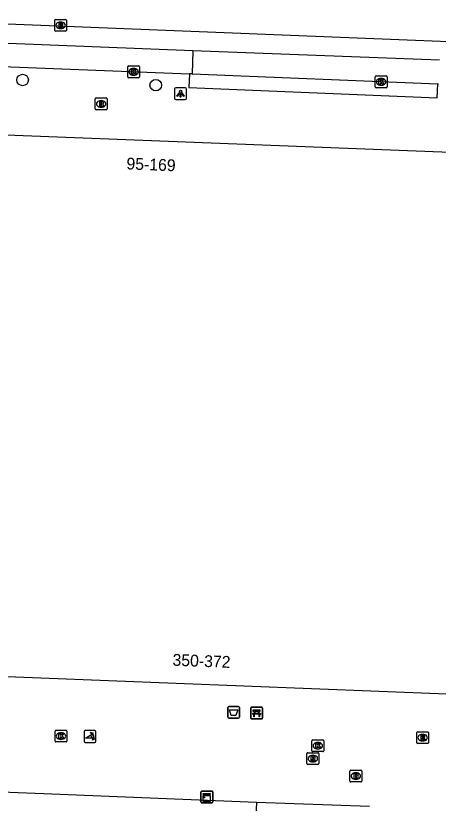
# Model space of a CAD drawing. Extents: x 160891 to 161384, y 386490 to 386907.
# Drawn here: x 161140.9 to 161176.7, y 386833.9 to 386900.6 of the extents above; entities that cross this region are included whole.
import ezdxf

# ---------------------------------------------------------------- set-up
doc = ezdxf.new("R2010")
doc.units = 0
for name, color, linetype in [('IMGEO_Afvalbak', 7, 'Continuous'), ('IMGEO_Bank', 7, 'Continuous'), ('IMGEO_Boom', 7, 'Continuous'), ('IMGEO_Brandkraan', 7, 'Continuous'), ('IMGEO_Kast', 7, 'Continuous'), ('IMGEO_Kolk', 7, 'Continuous'), ('IMGEO_Lichtpunt', 7, 'Continuous'), ('IMGEO_Pand', 7, 'Continuous'), ('IMGEO_Pand_nummerreeks', 7, 'Continuous'), ('IMGEO_Poller', 7, 'Continuous'), ('IMGEO_Rijbaan_lokaal_gesloten', 7, 'Continuous'), ('IMGEO_Rioolput', 7, 'Continuous'), ('IMGEO_Voetpad_open', 7, 'Continuous')]:
    doc.layers.add(name, color=color, linetype=linetype)

msp = doc.modelspace()

# ---------------------------------------------------------------- linework, layer by layer
at = {"layer": 'IMGEO_Afvalbak'}
for p, q in [((161158.851, 386841.169), (161158.851, 386841.969)), ((161158.851, 386841.969), (161158.851, 386841.169)), ((161158.951, 386842.069), (161159.741, 386842.069)), ((161159.741, 386842.069), (161158.951, 386842.069)), ((161159.841, 386841.969), (161159.841, 386841.169)), ((161159.841, 386841.169), (161159.841, 386841.969)), ((161159.741, 386841.069), (161158.951, 386841.069)), ((161158.951, 386841.069), (161159.741, 386841.069))]:
    msp.add_line(p, q, dxfattribs=at)
msp.add_lwpolyline([(161158.994, 386841.783), (161159.698, 386841.783), (161159.549, 386841.313), (161159.143, 386841.313), (161158.994, 386841.783)], dxfattribs=at)
for centre, start, end in [((161158.951, 386841.969), 90, 180), ((161158.951, 386841.969), 90, 180), ((161159.741, 386841.969), 0, 90), ((161159.741, 386841.969), 360, 90), ((161158.951, 386841.169), 180, 270), ((161158.951, 386841.169), 180, 270), ((161159.741, 386841.169), 270, 0), ((161159.741, 386841.169), 270, 0)]:
    msp.add_arc(centre, 0.1, start, end, dxfattribs=at)
at = {"layer": 'IMGEO_Bank'}
for p, q in [((161160.805, 386841.088), (161160.805, 386841.929)), ((161160.805, 386841.929), (161160.805, 386841.088)), ((161160.88, 386842.013), (161161.721, 386842.013)), ((161161.721, 386842.013), (161160.88, 386842.013)), ((161161.114, 386841.519), (161161.114, 386841.625)), ((161161.158, 386841.625), (161161.158, 386841.519)), ((161161.446, 386841.631), (161161.164, 386841.631)), ((161161.164, 386841.513), (161161.446, 386841.513)), ((161161.452, 386841.519), (161161.452, 386841.625)), ((161161.496, 386841.625), (161161.496, 386841.519)), ((161161.805, 386841.938), (161161.805, 386841.097)), ((161161.805, 386841.097), (161161.805, 386841.938)), ((161161.73, 386841.013), (161160.889, 386841.013)), ((161160.889, 386841.013), (161161.73, 386841.013)), ((161161.502, 386841.411), (161161.109, 386841.411))]:
    msp.add_line(p, q, dxfattribs=at)
for points in [[(161161.052, 386841.411), (161160.91, 386841.411), (161161.022, 386841.513), (161161.108, 386841.513)], [(161161.108, 386841.631), (161161.022, 386841.631), (161161.022, 386841.792), (161161.585, 386841.792), (161161.585, 386841.631), (161161.502, 386841.631)], [(161161.502, 386841.513), (161161.585, 386841.513), (161161.697, 386841.411), (161161.558, 386841.411)], [(161161.102, 386841.404), (161161.102, 386841.197), (161161.059, 386841.197), (161161.059, 386841.404)], [(161161.552, 386841.404), (161161.552, 386841.197), (161161.508, 386841.197), (161161.508, 386841.404)]]:
    msp.add_lwpolyline(points, dxfattribs=at)
for centre, radius, start, end in [((161160.883, 386841.935), 0.0779, 92.4484, 184.28452), ((161160.883, 386841.935), 0.0779, 92.4484, 184.28452), ((161161.107, 386841.624), 0.00671, 2.89567, 87.10433), ((161161.107, 386841.52), 0.00671, 272.89567, 357.10433), ((161161.164, 386841.624), 0.00671, 92.89567, 177.10433), ((161161.164, 386841.52), 0.00671, 182.89567, 267.10433), ((161161.446, 386841.624), 0.00671, 2.89567, 87.10433), ((161161.446, 386841.52), 0.00671, 272.89567, 357.10433), ((161161.503, 386841.624), 0.00671, 92.89567, 177.10433), ((161161.503, 386841.52), 0.00671, 182.89567, 267.10433), ((161161.727, 386841.935), 0.0779, 2.4484, 94.28452), ((161161.727, 386841.935), 0.0779, 2.4484, 94.28452), ((161160.883, 386841.091), 0.0779, 182.4484, 274.28452), ((161160.883, 386841.091), 0.0779, 182.4484, 274.28452), ((161161.052, 386841.404), 0.00671, 2.89567, 87.10433), ((161161.109, 386841.404), 0.00671, 92.89567, 177.10433), ((161161.501, 386841.404), 0.00671, 2.89567, 87.10433), ((161161.558, 386841.404), 0.00671, 92.89567, 177.10433), ((161161.727, 386841.091), 0.0779, 272.4484, 4.28452), ((161161.727, 386841.091), 0.0779, 272.4484, 4.28452)]:
    msp.add_arc(centre, radius, start, end, dxfattribs=at)
at = {"layer": 'IMGEO_Boom'}
for centre in [(161141.488, 386895.12), (161152.761, 386894.677)]:
    msp.add_circle(centre, 0.489, dxfattribs=at)
at = {"layer": 'IMGEO_Brandkraan'}
for p, q in [((161147.635, 386892.671), (161147.635, 386893.523)), ((161147.71, 386893.597), (161148.562, 386893.597)), ((161148.636, 386893.523), (161148.636, 386892.671)), ((161148.146, 386892.817), (161148.121, 386892.817)), ((161148.123, 386893.377), (161148.148, 386893.377)), ((161148.562, 386892.597), (161147.71, 386892.597)), ((161169.199, 386835.749), (161169.199, 386836.601)), ((161169.274, 386836.675), (161170.126, 386836.675)), ((161169.687, 386836.455), (161169.712, 386836.455)), ((161170.2, 386836.601), (161170.2, 386835.749)), ((161170.126, 386835.675), (161169.274, 386835.675)), ((161169.71, 386835.895), (161169.685, 386835.895))]:
    msp.add_line(p, q, dxfattribs=at)
for points in [[(161147.635, 386892.671), (161147.635, 386893.523)], [(161147.71, 386893.597), (161148.562, 386893.597)], [(161148.636, 386893.523), (161148.636, 386892.671)], [(161147.983, 386893.297), (161147.983, 386892.897), (161148.196, 386892.897)], [(161148.214, 386893.297), (161147.983, 386893.297)], [(161148.162, 386893.216), (161148.108, 386893.216), (161148.108, 386893.14)], [(161148.108, 386893.14), (161148.161, 386893.14)], [(161148.17, 386893.064), (161148.108, 386893.064), (161148.108, 386892.983)], [(161148.108, 386892.983), (161148.17, 386892.983)], [(161148.562, 386892.597), (161147.71, 386892.597)], [(161169.199, 386835.749), (161169.199, 386836.601)], [(161169.274, 386836.675), (161170.126, 386836.675)], [(161169.547, 386836.375), (161169.547, 386835.975), (161169.76, 386835.975)], [(161169.778, 386836.375), (161169.547, 386836.375)], [(161169.726, 386836.294), (161169.672, 386836.294), (161169.672, 386836.218)], [(161169.672, 386836.218), (161169.725, 386836.218)], [(161169.734, 386836.142), (161169.672, 386836.142), (161169.672, 386836.061)], [(161170.2, 386836.601), (161170.2, 386835.749)], [(161170.126, 386835.675), (161169.274, 386835.675)], [(161169.672, 386836.061), (161169.734, 386836.061)]]:
    msp.add_lwpolyline(points, dxfattribs=at)
for centre, radius, start, end in [((161147.712, 386893.521), 0.0765, 91.55205, 178.44795), ((161147.712, 386893.521), 0.0765, 91.55205, 178.44795), ((161148.56, 386893.521), 0.0765, 1.55205, 88.44795), ((161148.56, 386893.521), 0.0765, 1.55205, 88.44795), ((161148.163, 386893.178), 0.0379, 267.82845, 90.93552), ((161148.171, 386893.023), 0.0404, 269.87594, 90.50774), ((161148.202, 386893.148), 0.251, 268.66757, 293.53466), ((161148.218, 386893.152), 0.145, 59.4692, 91.53667), ((161148.243, 386893.199), 0.0922, 285.51372, 58.15012), ((161148.248, 386893.007), 0.105, 301.31148, 78.98903), ((161147.712, 386892.673), 0.0765, 181.55205, 268.44795), ((161147.712, 386892.673), 0.0765, 181.55205, 268.44795), ((161148.56, 386892.673), 0.0765, 271.55205, 358.44795), ((161148.56, 386892.673), 0.0765, 271.55205, 358.44795), ((161169.276, 386836.599), 0.0765, 91.55205, 178.44795), ((161169.276, 386836.599), 0.0765, 91.55205, 178.44795), ((161169.727, 386836.256), 0.0379, 267.82845, 90.93552), ((161169.735, 386836.101), 0.0404, 269.87594, 90.50774), ((161169.782, 386836.23), 0.145, 59.4692, 91.53667), ((161169.807, 386836.277), 0.0922, 285.51372, 58.15012), ((161169.812, 386836.085), 0.105, 301.31148, 78.98903), ((161170.124, 386836.599), 0.0765, 1.55205, 88.44795), ((161170.124, 386836.599), 0.0765, 1.55205, 88.44795), ((161169.276, 386835.751), 0.0765, 181.55205, 268.44795), ((161169.276, 386835.751), 0.0765, 181.55205, 268.44795), ((161169.766, 386836.226), 0.251, 268.66757, 293.53466), ((161170.124, 386835.751), 0.0765, 271.55205, 358.44795), ((161170.124, 386835.751), 0.0765, 271.55205, 358.44795)]:
    msp.add_arc(centre, radius, start, end, dxfattribs=at)
for centre, major_axis, ratio, start_param, end_param in [((161148.122, 386893.097), (-0.387, 0.002), 0.722429, 4.712389, 7.853982), ((161148.147, 386893.097), (-0.39, 0.002), 0.717154, 1.570796, 4.712389), ((161169.686, 386836.175), (-0.387, 0.002), 0.722429, 4.712389, 7.853982), ((161169.711, 386836.175), (-0.39, 0.002), 0.717154, 1.570796, 4.712389)]:
    msp.add_ellipse(centre, major_axis=major_axis, ratio=ratio, start_param=start_param, end_param=end_param, dxfattribs=at)
at = {"layer": 'IMGEO_Kast'}
for p, q in [((161156.584, 386833.979), (161156.584, 386834.82)), ((161156.584, 386834.82), (161156.584, 386833.979)), ((161156.659, 386834.904), (161157.5, 386834.904)), ((161157.5, 386834.904), (161156.659, 386834.904)), ((161157.584, 386834.829), (161157.584, 386833.988)), ((161157.584, 386833.988), (161157.584, 386834.829)), ((161157.509, 386833.904), (161156.668, 386833.904)), ((161156.668, 386833.904), (161157.509, 386833.904))]:
    msp.add_line(p, q, dxfattribs=at)
for points in [[(161156.779, 386834.694), (161157.379, 386834.694), (161157.379, 386834.609), (161156.779, 386834.609), (161156.779, 386834.694)], [(161156.779, 386834.519), (161157.379, 386834.519), (161157.379, 386834.03), (161156.779, 386834.03), (161156.779, 386834.519)]]:
    msp.add_lwpolyline(points, dxfattribs=at)
msp.add_circle((161156.863, 386834.368), 0.0377, dxfattribs=at)
for centre, start, end in [((161156.662, 386834.826), 92.4484, 184.28452), ((161156.662, 386834.826), 92.4484, 184.28452), ((161157.506, 386834.826), 2.4484, 94.28452), ((161157.506, 386834.826), 2.4484, 94.28452), ((161156.662, 386833.982), 182.4484, 274.28452), ((161156.662, 386833.982), 182.4484, 274.28452), ((161157.506, 386833.982), 272.4484, 4.28452), ((161157.506, 386833.982), 272.4484, 4.28452)]:
    msp.add_arc(centre, 0.0779, start, end, dxfattribs=at)
at = {"layer": 'IMGEO_Kolk'}
for p, q in [((161150.383, 386895.385), (161150.383, 386896.237)), ((161150.458, 386896.311), (161151.31, 386896.311)), ((161151.384, 386896.237), (161151.384, 386895.385)), ((161150.894, 386895.531), (161150.869, 386895.531)), ((161150.871, 386896.091), (161150.896, 386896.091)), ((161151.31, 386895.311), (161150.458, 386895.311)), ((161171.341, 386894.538), (161171.341, 386895.39)), ((161171.416, 386895.464), (161172.268, 386895.464)), ((161171.829, 386895.244), (161171.854, 386895.244)), ((161172.342, 386895.39), (161172.342, 386894.538)), ((161172.268, 386894.464), (161171.416, 386894.464)), ((161171.852, 386894.684), (161171.827, 386894.684)), ((161144.236, 386839.134), (161144.236, 386839.986)), ((161144.311, 386840.06), (161145.163, 386840.06)), ((161144.724, 386839.84), (161144.749, 386839.84)), ((161145.237, 386839.986), (161145.237, 386839.134)), ((161145.163, 386839.06), (161144.311, 386839.06)), ((161144.747, 386839.28), (161144.722, 386839.28)), ((161165.987, 386838.316), (161165.987, 386839.168)), ((161166.062, 386839.242), (161166.914, 386839.242)), ((161166.475, 386839.022), (161166.5, 386839.022)), ((161166.988, 386839.168), (161166.988, 386838.316)), ((161166.914, 386838.242), (161166.062, 386838.242)), ((161166.498, 386838.462), (161166.473, 386838.462))]:
    msp.add_line(p, q, dxfattribs=at)
for points in [[(161150.383, 386895.385), (161150.383, 386896.237)], [(161150.458, 386896.311), (161151.31, 386896.311)], [(161151.384, 386896.237), (161151.384, 386895.385)], [(161150.704, 386896.011), (161150.827, 386896.011), (161150.827, 386895.86), (161150.957, 386896.011), (161151.121, 386896.011), (161150.975, 386895.86), (161151.128, 386895.611), (161150.976, 386895.611), (161150.891, 386895.775), (161150.827, 386895.708), (161150.827, 386895.611), (161150.704, 386895.611), (161150.704, 386896.011)], [(161151.31, 386895.311), (161150.458, 386895.311)], [(161171.341, 386894.538), (161171.341, 386895.39)], [(161171.416, 386895.464), (161172.268, 386895.464)], [(161171.662, 386895.164), (161171.785, 386895.164), (161171.785, 386895.013), (161171.915, 386895.164), (161172.079, 386895.164), (161171.933, 386895.013), (161172.086, 386894.764), (161171.934, 386894.764), (161171.849, 386894.928), (161171.785, 386894.861), (161171.785, 386894.764), (161171.662, 386894.764), (161171.662, 386895.164)], [(161172.342, 386895.39), (161172.342, 386894.538)], [(161172.268, 386894.464), (161171.416, 386894.464)], [(161144.236, 386839.134), (161144.236, 386839.986)], [(161144.311, 386840.06), (161145.163, 386840.06)], [(161144.557, 386839.76), (161144.68, 386839.76), (161144.68, 386839.609), (161144.81, 386839.76), (161144.974, 386839.76), (161144.828, 386839.609), (161144.981, 386839.36), (161144.829, 386839.36), (161144.744, 386839.524), (161144.68, 386839.457), (161144.68, 386839.36), (161144.557, 386839.36), (161144.557, 386839.76)], [(161145.237, 386839.986), (161145.237, 386839.134)], [(161145.163, 386839.06), (161144.311, 386839.06)], [(161165.987, 386838.316), (161165.987, 386839.168)], [(161166.062, 386839.242), (161166.914, 386839.242)], [(161166.308, 386838.942), (161166.431, 386838.942), (161166.431, 386838.791), (161166.561, 386838.942), (161166.725, 386838.942), (161166.579, 386838.791), (161166.732, 386838.542), (161166.58, 386838.542), (161166.495, 386838.706), (161166.431, 386838.639), (161166.431, 386838.542), (161166.308, 386838.542), (161166.308, 386838.942)], [(161166.988, 386839.168), (161166.988, 386838.316)], [(161166.914, 386838.242), (161166.062, 386838.242)]]:
    msp.add_lwpolyline(points, dxfattribs=at)
for centre, start, end in [((161150.46, 386896.235), 91.55205, 178.44795), ((161150.46, 386896.235), 91.55205, 178.44795), ((161151.308, 386896.235), 1.55205, 88.44795), ((161151.308, 386896.235), 1.55205, 88.44795), ((161150.46, 386895.387), 181.55205, 268.44795), ((161150.46, 386895.387), 181.55205, 268.44795), ((161151.308, 386895.387), 271.55205, 358.44795), ((161151.308, 386895.387), 271.55205, 358.44795), ((161171.418, 386895.388), 91.55205, 178.44795), ((161171.418, 386895.388), 91.55205, 178.44795), ((161172.266, 386895.388), 1.55205, 88.44795), ((161172.266, 386895.388), 1.55205, 88.44795), ((161171.418, 386894.54), 181.55205, 268.44795), ((161171.418, 386894.54), 181.55205, 268.44795), ((161172.266, 386894.54), 271.55205, 358.44795), ((161172.266, 386894.54), 271.55205, 358.44795), ((161144.313, 386839.984), 91.55205, 178.44795), ((161144.313, 386839.984), 91.55205, 178.44795), ((161145.161, 386839.984), 1.55205, 88.44795), ((161145.161, 386839.984), 1.55205, 88.44795), ((161144.313, 386839.136), 181.55205, 268.44795), ((161144.313, 386839.136), 181.55205, 268.44795), ((161145.161, 386839.136), 271.55205, 358.44795), ((161145.161, 386839.136), 271.55205, 358.44795), ((161166.064, 386839.166), 91.55205, 178.44795), ((161166.064, 386839.166), 91.55205, 178.44795), ((161166.912, 386839.166), 1.55205, 88.44795), ((161166.912, 386839.166), 1.55205, 88.44795), ((161166.064, 386838.318), 181.55205, 268.44795), ((161166.064, 386838.318), 181.55205, 268.44795), ((161166.912, 386838.318), 271.55205, 358.44795), ((161166.912, 386838.318), 271.55205, 358.44795)]:
    msp.add_arc(centre, 0.0765, start, end, dxfattribs=at)
for centre, major_axis, ratio, start_param, end_param in [((161150.87, 386895.811), (-0.387, 0.002), 0.722429, 4.712389, 7.853982), ((161150.895, 386895.811), (-0.39, 0.002), 0.717154, 1.570796, 4.712389), ((161171.828, 386894.964), (-0.387, 0.002), 0.722429, 4.712389, 7.853982), ((161171.853, 386894.964), (-0.39, 0.002), 0.717154, 1.570796, 4.712389), ((161144.723, 386839.56), (-0.387, 0.002), 0.722429, 4.712389, 7.853982), ((161144.748, 386839.56), (-0.39, 0.002), 0.717154, 1.570796, 4.712389), ((161166.474, 386838.742), (-0.387, 0.002), 0.722429, 4.712389, 7.853982), ((161166.499, 386838.742), (-0.39, 0.002), 0.717154, 1.570796, 4.712389)]:
    msp.add_ellipse(centre, major_axis=major_axis, ratio=ratio, start_param=start_param, end_param=end_param, dxfattribs=at)
at = {"layer": 'IMGEO_Lichtpunt'}
for p, q in [((161154.357, 386894.358), (161154.357, 386893.551)), ((161154.357, 386894.358), (161154.357, 386893.551)), ((161155.259, 386894.453), (161154.451, 386894.453)), ((161155.259, 386894.453), (161154.451, 386894.453)), ((161155.353, 386893.551), (161155.353, 386894.358)), ((161155.353, 386893.551), (161155.353, 386894.358)), ((161154.451, 386893.457), (161155.259, 386893.457)), ((161154.451, 386893.457), (161155.259, 386893.457))]:
    msp.add_line(p, q, dxfattribs=at)
for points in [[(161154.731, 386894.022), (161154.77, 386893.994), (161154.582, 386893.732), (161154.544, 386893.759), (161154.731, 386894.022)], [(161154.833, 386893.974), (161154.88, 386893.974), (161154.88, 386893.652), (161154.833, 386893.652), (161154.833, 386893.974)], [(161154.943, 386893.994), (161154.981, 386894.021), (161155.168, 386893.759), (161155.129, 386893.731), (161154.943, 386893.994)]]:
    msp.add_lwpolyline(points, dxfattribs=at)
msp.add_circle((161154.856, 386894.156), 0.0994, dxfattribs=at)
for centre, start, end in [((161154.451, 386894.358), 90, 180), ((161154.451, 386894.358), 90, 180), ((161155.259, 386894.358), 0, 90), ((161155.259, 386894.358), 0, 90), ((161154.451, 386893.551), 180, 270), ((161154.451, 386893.551), 180, 270), ((161155.259, 386893.551), 270, 0), ((161155.259, 386893.551), 270, 360)]:
    msp.add_arc(centre, 0.0946, start, end, dxfattribs=at)
at = {"layer": 'IMGEO_Pand'}
for points in [[(161196.381, 386887.886), (161196.395, 386888.23), (161188.186, 386888.554), (161178.427, 386888.94), (161127.058, 386890.969)], [(161194.586, 386842.427), (161120.067, 386845.369), (161120.551, 386857.609)], [(161139.684, 386834.849), (161143.958, 386834.674), (161161.282, 386833.963)], [(161161.282, 386833.963), (161160.709, 386819.875), (161160.411, 386812.554), (161160.119, 386805.384), (161159.627, 386793.285), (161159.236, 386783.673), (161158.95, 386776.656), (161158.648, 386769.233), (161158.228, 386758.915)]]:
    msp.add_lwpolyline(points, dxfattribs=at)
at = {"layer": 'IMGEO_Poller'}
for p, q in [((161146.698, 386839.927), (161146.698, 386839.12)), ((161146.698, 386839.927), (161146.698, 386839.12)), ((161147.6, 386840.022), (161146.792, 386840.022)), ((161147.6, 386840.022), (161146.792, 386840.022)), ((161147.694, 386839.12), (161147.694, 386839.927)), ((161147.694, 386839.12), (161147.694, 386839.927)), ((161146.792, 386839.025), (161147.6, 386839.025)), ((161146.792, 386839.025), (161147.6, 386839.025))]:
    msp.add_line(p, q, dxfattribs=at)
for points in [[(161147.333, 386839.378), (161146.82, 386839.378), (161147.25, 386839.653)], [(161147.377, 386839.751), (161147.365, 386839.678), (161147.24, 386839.883)], [(161147.24, 386839.883), (161147.471, 386839.817), (161147.4, 386839.785)], [(161147.393, 386839.206), (161147.459, 386839.437), (161147.489, 386839.369)], [(161147.525, 386839.342), (161147.597, 386839.331), (161147.393, 386839.206)]]:
    msp.add_lwpolyline(points, dxfattribs=at)
for centre, radius, start, end in [((161146.792, 386839.927), 0.0946, 90, 180), ((161146.792, 386839.927), 0.0946, 90, 180), ((161147.005, 386839.428), 0.332, 351.32473, 42.4854), ((161147.019, 386839.438), 0.476, 351.75274, 41.16905), ((161147.019, 386839.438), 0.516, 349.35686, 42.29123), ((161147.6, 386839.927), 0.0946, 0, 90), ((161147.6, 386839.927), 0.0946, 0, 90), ((161146.792, 386839.12), 0.0946, 180, 270), ((161146.792, 386839.12), 0.0946, 180, 270), ((161147.6, 386839.12), 0.0946, 270, 0), ((161147.6, 386839.12), 0.0946, 270, 0)]:
    msp.add_arc(centre, radius, start, end, dxfattribs=at)
at = {"layer": 'IMGEO_Rijbaan_lokaal_gesloten'}
for points in [[(161123.263, 386900.56), (161248.069, 386895.57), (161278.544, 386894.358), (161279.11, 386894.349)], [(161155.904, 386897.594), (161123.188, 386898.901)], [(161155.904, 386897.594), (161155.851, 386895.628)], [(161176.778, 386896.8), (161155.904, 386897.594)], [(161155.851, 386895.628), (161176.66, 386894.802)], [(161176.66, 386894.802), (161176.703, 386894.8)]]:
    msp.add_lwpolyline(points, dxfattribs=at)
at = {"layer": 'IMGEO_Rioolput'}
for p, q in [((161144.202, 386899.324), (161144.202, 386900.176)), ((161144.277, 386900.25), (161145.129, 386900.25)), ((161145.203, 386900.176), (161145.203, 386899.324)), ((161144.69, 386900.03), (161144.715, 386900.03)), ((161145.129, 386899.25), (161144.277, 386899.25)), ((161144.713, 386899.47), (161144.688, 386899.47)), ((161174.859, 386839.002), (161174.859, 386839.854)), ((161174.934, 386839.928), (161175.786, 386839.928)), ((161175.347, 386839.708), (161175.372, 386839.708)), ((161175.86, 386839.854), (161175.86, 386839.002)), ((161175.786, 386838.928), (161174.934, 386838.928)), ((161175.37, 386839.148), (161175.345, 386839.148)), ((161165.641, 386838.151), (161166.493, 386838.151)), ((161165.566, 386837.225), (161165.566, 386838.077)), ((161166.054, 386837.931), (161166.079, 386837.931)), ((161166.567, 386838.077), (161166.567, 386837.225)), ((161166.493, 386837.151), (161165.641, 386837.151)), ((161166.077, 386837.371), (161166.052, 386837.371))]:
    msp.add_line(p, q, dxfattribs=at)
for points in [[(161144.202, 386899.324), (161144.202, 386900.176)], [(161144.277, 386900.25), (161145.129, 386900.25)], [(161145.203, 386900.176), (161145.203, 386899.324)], [(161144.791, 386899.948), (161144.539, 386899.95), (161144.539, 386899.55)], [(161144.539, 386899.55), (161144.663, 386899.55), (161144.663, 386899.712), (161144.674, 386899.712)], [(161144.717, 386899.869), (161144.663, 386899.869), (161144.663, 386899.788)], [(161144.663, 386899.788), (161144.715, 386899.788)], [(161144.721, 386899.683), (161144.792, 386899.55), (161144.932, 386899.55), (161144.867, 386899.676)], [(161145.129, 386899.25), (161144.277, 386899.25)], [(161174.859, 386839.002), (161174.859, 386839.854)], [(161174.934, 386839.928), (161175.786, 386839.928)], [(161175.448, 386839.626), (161175.196, 386839.628), (161175.196, 386839.228)], [(161175.374, 386839.547), (161175.32, 386839.547), (161175.32, 386839.466)], [(161175.32, 386839.466), (161175.372, 386839.466)], [(161175.86, 386839.854), (161175.86, 386839.002)], [(161175.786, 386838.928), (161174.934, 386838.928)], [(161175.196, 386839.228), (161175.32, 386839.228), (161175.32, 386839.39), (161175.331, 386839.39)], [(161175.378, 386839.361), (161175.449, 386839.228), (161175.589, 386839.228), (161175.524, 386839.354)], [(161165.641, 386838.151), (161166.493, 386838.151)], [(161165.566, 386837.225), (161165.566, 386838.077)], [(161166.155, 386837.849), (161165.903, 386837.851), (161165.903, 386837.451)], [(161165.903, 386837.451), (161166.027, 386837.451), (161166.027, 386837.613), (161166.038, 386837.613)], [(161166.081, 386837.77), (161166.027, 386837.77), (161166.027, 386837.689)], [(161166.027, 386837.689), (161166.079, 386837.689)], [(161166.085, 386837.584), (161166.156, 386837.451), (161166.296, 386837.451), (161166.231, 386837.577)], [(161166.567, 386838.077), (161166.567, 386837.225)], [(161166.493, 386837.151), (161165.641, 386837.151)]]:
    msp.add_lwpolyline(points, dxfattribs=at)
for centre, radius, start, end in [((161144.279, 386900.174), 0.0765, 91.55205, 178.44795), ((161144.279, 386900.174), 0.0765, 91.55205, 178.44795), ((161145.127, 386900.174), 0.0765, 1.55205, 88.44795), ((161145.127, 386900.174), 0.0765, 1.55205, 88.44795), ((161144.673, 386899.659), 0.0533, 26.02933, 88.69889), ((161144.699, 386899.977), 0.19, 274.7715, 282.96867), ((161144.723, 386899.773), 0.0964, 77.00612, 93.18647), ((161144.737, 386899.83), 0.0378, 276.66336, 79.67722), ((161144.79, 386899.838), 0.109, 350.36119, 89.41601), ((161144.788, 386899.838), 0.112, 277.58423, 350.98172), ((161144.772, 386899.623), 0.108, 29.51342, 73.79051), ((161144.279, 386899.326), 0.0765, 181.55205, 268.44795), ((161144.279, 386899.326), 0.0765, 181.55205, 268.44795), ((161145.127, 386899.326), 0.0765, 271.55205, 358.44795), ((161145.127, 386899.326), 0.0765, 271.55205, 358.44795), ((161174.936, 386839.852), 0.0765, 91.55205, 178.44795), ((161174.936, 386839.852), 0.0765, 91.55205, 178.44795), ((161175.356, 386839.655), 0.19, 274.7715, 282.96867), ((161175.38, 386839.451), 0.0964, 77.00612, 93.18647), ((161175.394, 386839.508), 0.0378, 276.66336, 79.67722), ((161175.447, 386839.516), 0.109, 350.36119, 89.41601), ((161175.445, 386839.516), 0.112, 277.58423, 350.98172), ((161175.784, 386839.852), 0.0765, 1.55205, 88.44795), ((161175.784, 386839.852), 0.0765, 1.55205, 88.44795), ((161174.936, 386839.004), 0.0765, 181.55205, 268.44795), ((161174.936, 386839.004), 0.0765, 181.55205, 268.44795), ((161175.33, 386839.337), 0.0533, 26.02933, 88.69889), ((161175.429, 386839.301), 0.108, 29.51342, 73.79051), ((161175.784, 386839.004), 0.0765, 271.55205, 358.44795), ((161175.784, 386839.004), 0.0765, 271.55205, 358.44795), ((161165.643, 386838.075), 0.0765, 91.55205, 178.44795), ((161165.643, 386838.075), 0.0765, 91.55205, 178.44795), ((161166.491, 386838.075), 0.0765, 1.55205, 88.44795), ((161166.491, 386838.075), 0.0765, 1.55205, 88.44795), ((161166.037, 386837.56), 0.0533, 26.02933, 88.69889), ((161166.063, 386837.878), 0.19, 274.7715, 282.96867), ((161166.087, 386837.674), 0.0964, 77.00612, 93.18647), ((161166.101, 386837.731), 0.0378, 276.66336, 79.67722), ((161166.154, 386837.739), 0.109, 350.36119, 89.41601), ((161166.152, 386837.739), 0.112, 277.58423, 350.98172), ((161166.136, 386837.524), 0.108, 29.51342, 73.79051), ((161165.643, 386837.227), 0.0765, 181.55205, 268.44795), ((161165.643, 386837.227), 0.0765, 181.55205, 268.44795), ((161166.491, 386837.227), 0.0765, 271.55205, 358.44795), ((161166.491, 386837.227), 0.0765, 271.55205, 358.44795)]:
    msp.add_arc(centre, radius, start, end, dxfattribs=at)
for centre, major_axis, ratio, start_param, end_param in [((161144.689, 386899.75), (-0.387, 0.002), 0.722429, 4.712389, 7.853982), ((161144.714, 386899.75), (-0.39, 0.002), 0.717154, 1.570796, 4.712389), ((161175.346, 386839.428), (-0.387, 0.002), 0.722429, 4.712389, 7.853982), ((161175.371, 386839.428), (-0.39, 0.002), 0.717154, 1.570796, 4.712389), ((161166.053, 386837.651), (-0.387, 0.002), 0.722429, 4.712389, 7.853982), ((161166.078, 386837.651), (-0.39, 0.002), 0.717154, 1.570796, 4.712389)]:
    msp.add_ellipse(centre, major_axis=major_axis, ratio=ratio, start_param=start_param, end_param=end_param, dxfattribs=at)
at = {"layer": 'IMGEO_Voetpad_open'}
for points in [[(161125.921, 386896.787), (161127.859, 386896.678), (161137.577, 386896.347), (161155.616, 386895.637)], [(161155.616, 386895.637), (161155.57, 386894.474), (161176.601, 386893.617), (161176.66, 386894.802)], [(161155.851, 386895.628), (161155.616, 386895.637)], [(161161.282, 386833.963), (161170.867, 386833.628)]]:
    msp.add_lwpolyline(points, dxfattribs=at)

# ---------------------------------------------------------------- texts
at = {"layer": 'IMGEO_Pand_nummerreeks'}
for s, rotation, p in [('95-169', 357.73808, (161150.263, 386887.55)), ('350-372', 357.73914, (161154.163, 386845.524))]:
    msp.add_text(s, height=1, rotation=rotation, dxfattribs=at).set_placement(p)

doc.saveas('drawing.dxf')
